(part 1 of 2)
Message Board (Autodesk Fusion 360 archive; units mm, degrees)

design "Message Board" references "MatrixPortal Mount", "Side Panel", "16x32 LED Panel", "Connector Bracket", "5778 Matrix Portal S3", "Top Panel with Cutout", "Top/Bottom Panel"
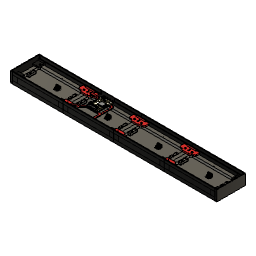
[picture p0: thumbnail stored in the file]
component_insert "Component Insert1"
component_insert "Component Insert2"
component_insert "Component Insert3"
component_insert "Component Insert4"
component_insert "Component Insert5"
component_insert "Component Insert6"
component_insert "Component Insert7"
component_insert "Component Insert8"
component_insert "Component Insert9"
component_insert "Component Insert10"
component_insert "Component Insert12"
component_insert "Component Insert13"
component_insert "Component Insert14"
component_insert "Component Insert16"
component_insert "Component Insert17"
component_insert "Component Insert18"
component_insert "Component Insert19"
component_insert "Component Insert20"
component_insert "Component Insert21"
component_insert "Component Insert22"
component_insert "Component Insert23"
position "Position1"
sketch "Sketch1" plane through (0, 0, 0) normal (0, 0, 1) x axis (1, 0, 0)
  line L1 (-777, 0) -> (0, 0)
  line L2 (-777, -103.75) -> (-777, 0)
  line L3 (0, -103.75) -> (-777, -103.75)
  line L4 (0, 0) -> (0, -103.75)
  point P1 (0, 0)
  point P2 (0, 0)
  point P3 (-777, 0)
  point P5 (0, -103.75)
  horizontal L1
  vertical L2
  horizontal L3
  vertical L4
  coincident P1 P2
  dimension "d1" distance P2 P3 = 777
  dimension "d2" distance P2 P5 = 103.75
extrude "Extrude1" new body sketch "Sketch1" along normal blind 3 bodies "Acrylic Panel"
move "Move1"
position "Position2"
component_insert "Component Insert24"
named bodies: "Acrylic Panel"

design "Side Panel"
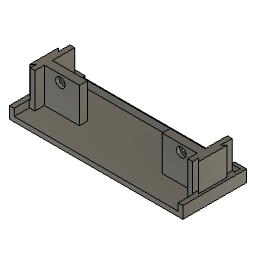
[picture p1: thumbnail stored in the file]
sketch "Sketch1" plane through (0, 0, 0) normal (0, 0, 1) x axis (1, 0, 0)
  line L1 (109, 0) -> (0, 0)
  line L2 (109, 40) -> (109, 0)
  line L3 (0, 40) -> (109, 40)
  line L4 (0, 0) -> (0, 40)
  line L5 (106, 0) -> (3, 0)
  line L6 (106, 34.5) -> (106, 0)
  line L7 (3, 38) -> (105.9999, 38)
  line L8 (3, 0) -> (3, 34.5)
  line L9 (1.5, 11.25) -> (1.5, 29.25)
  line L10 (3.5, 13.25) -> (1.5, 11.25)
  line L11 (3.5, 9.5) -> (3.5, 13.25)
  line L12 (6.5, 9.5) -> (3.5, 9.5)
  line L13 (6.5, 15.5) -> (6.5, 9.5)
  line L14 (28.5, 15.5) -> (6.5, 15.5)
  line L15 (28.5, 20.5) -> (28.5, 15.5)
  line L16 (6.5, 20.5) -> (28.5, 20.5)
  line L17 (6.5, 34.5) -> (6.5, 20.5)
  line L18 (3.5, 34.5) -> (6.5, 34.5)
  line L19 (3.5, 27.25) -> (1.5, 29.25)
  line L20 (3.5, 34.5) -> (3.5, 27.25)
  line L21 (54.5, 40) -> (54.5, 0)
  line L22 (102.5, 9.5) -> (105.5, 9.5)
  line L23 (102.5, 15.5) -> (102.5, 9.5)
  line L24 (80.5, 15.5) -> (102.5, 15.5)
  line L25 (80.5, 20.5) -> (80.5, 15.5)
  line L26 (102.5, 20.5) -> (80.5, 20.5)
  line L27 (102.5, 34.5) -> (102.5, 20.5)
  line L28 (105.5, 34.5) -> (102.5, 34.5)
  line L29 (105.5, 34.5) -> (105.5, 27.25)
  line L30 (105.5, 27.25) -> (107.5, 29.25)
  line L31 (107.5, 11.25) -> (107.5, 29.25)
  line L32 (105.5, 13.25) -> (107.5, 11.25)
  line L33 (105.5, 9.5) -> (105.5, 13.25)
  line L34 (3, 34.5) -> (3.5, 34.5)
  line L35 (3, 9.5) -> (3.5, 9.5)
  line L36 (106, 9.5) -> (105.5, 9.5)
  line L37 (106, 34.5) -> (105.5, 34.5)
  line L38 (2, 38) -> (3, 38)
  line L39 (2, 34.5) -> (2, 38)
  line L40 (3, 34.5) -> (2, 34.5)
  line L41 (107, 38) -> (105.9999, 38)
  line L42 (107, 34.5) -> (106, 34.5)
  line L43 (107, 38) -> (107, 34.5)
  point P1 (0, 0)
  point P2 (0, 0)
  point P6 (3, 0)
  point P22 (54.5, 0)
  point P23 (54.5, 40)
  point P10 (1.5, 29.25)
  point P33 (107.5, 29.25)
  point P11 (1.5, 11.25)
  point P34 (107.5, 11.25)
  point P12 (3.5, 13.25)
  point P35 (105.5, 13.25)
  point P13 (3.5, 9.5)
  point P24 (105.5, 9.5)
  point P14 (6.5, 9.5)
  point P25 (102.5, 9.5)
  point P15 (6.5, 15.5)
  point P26 (102.5, 15.5)
  point P16 (28.5, 15.5)
  point P27 (80.5, 15.5)
  point P17 (28.5, 20.5)
  point P28 (80.5, 20.5)
  point P18 (6.5, 20.5)
  point P29 (102.5, 20.5)
  point P19 (6.5, 34.5)
  point P30 (102.5, 34.5)
  point P20 (3.5, 34.5)
  point P31 (105.5, 34.5)
  point P21 (3.5, 27.25)
  point P32 (105.5, 27.25)
  point P37 (3, 9.5)
  point P38 (105.5, 9.5)
  point P40 (105.5, 34.5)
  point P36 (3, 34.5)
  point P41 (106, 34.5)
  point P39 (106, 9.5)
  point P5 (0, 40)
  point P43 (2, 34.5)
  point P45 (107, 34.5)
  horizontal L1
  vertical L2
  horizontal L3
  vertical L4
  coincident P1 P2
  horizontal L5
  vertical L6
  horizontal L7
  vertical L8
  coincident L1 P6
  parallel L4 L9
  parallel L8 L11
  perpendicular L11 L12
  perpendicular L12 L13
  perpendicular L13 L14
  perpendicular L14 L15
  perpendicular L15 L16
  perpendicular L16 L17
  perpendicular L8 L18
  vertical L20
  midpoint L5 P22
  midpoint L3 P23
  symmetric P10 L21 P33
  symmetric P11 L21 P34
  symmetric P12 L21 P35
  symmetric P13 L21 P24
  symmetric P14 L21 P25
  symmetric P15 L21 P26
  symmetric P16 L21 P27
  symmetric P17 L21 P28
  symmetric P18 L21 P29
  symmetric P19 L21 P30
  symmetric P20 L21 P31
  symmetric P21 L21 P32
  perpendicular L8 L34
  coincident L8 P37
  perpendicular L8 L35
  symmetric P13 L21 P38
  symmetric P20 L21 P40
  symmetric L21 P36 P41
  symmetric L21 P37 P39
  perpendicular L8 L38
  perpendicular L38 L39
  horizontal L40
  perpendicular L6 L41
  perpendicular L6 L42
  vertical L43
  dimension "d2" distance P2 P5 = 40
  dimension "d3" distance L4 L8 = 3
  dimension "d4" distance L2 L6 = 3
  dimension "d5" distance L3 L7 = 2
  dimension "d6" distance P10 P11 = 18
  dimension "d8" distance P13 P14 = 3
  dimension "d9" distance P14 P15 = 6
  dimension "d10" distance P16 P17 = 5
  dimension "d11" distance P17 P18 = 22
  dimension "d12" distance P18 P19 = 14
  dimension "d13" distance P19 P20 = 3
  dimension "d15" distance L9 L11 = 2
  dimension "d16" distance L9 L20 = 2
  dimension "d17" distance P10 L18 = 5.25
  dimension "d18" distance L3 P10 = 10.75
  dimension "d19" distance L4 L9 = 1.5
  dimension "d26" angle L19 L20 = 45
  dimension "d27" angle L10 L11 = 45
  dimension "d54" distance L17 L27 = 96
  dimension "d58" distance P36 P43 = 1
  dimension "d59" distance P41 P45 = 1
extrude "Extrude1" new body sketch "Sketch1" profile of L1 L2 L3 L4 L5 L6 L7 L8 L9 L10 L11 L12 L13 L14 L15 L16 L17 L18 L19 L20 L22 L23 L24 L25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 along normal blind 3
extrude "Extrude2" add sketch "Sketch1" profile of L1 L2 L3 L4 L6 L7 L8 L9 L10 L11 L12 L13 L14 L15 L16 L17 L18 L19 L20 L22 L23 L24 L25 L26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 along normal blind 7.5
extrude "Extrude3" add sketch "Sketch1" profile of L6 L8 L9 L10 L11 L12 L13 L14 L15 L16 L17 L18 L19 L20 L22 L23 L24 L25 L26 L27 L28 L29 L30 L31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 along normal blind 25
sketch "Sketch2" plane through (0, 0, 7.5) normal (0, 0, 1) x axis (-1, 0, 0)
  line L1 (-107.5, -29.25) -> (-105.5, -27.25)
  line L2 (-107.5, -11.25) -> (-107.5, -29.25)
  line L3 (-105.5, -13.25) -> (-107.5, -11.25)
  line L4 (-105.5, -9.5) -> (-105.5, -13.25)
  line L5 (-106, -9.5) -> (-105.5, -9.5)
  line L6 (-109, 0) -> (-106, 0)
  line L7 (-109, -40) -> (-109, 0)
  line L8 (0, -40) -> (-109, -40)
  line L9 (0, 0) -> (0, -40)
  line L10 (-3.5, -9.5) -> (-3, -9.5)
  line L11 (-3.5, -13.25) -> (-3.5, -9.5)
  line L12 (-1.5, -11.25) -> (-3.5, -13.25)
  line L13 (-1.5, -29.25) -> (-1.5, -11.25)
  line L14 (-3.5, -27.25) -> (-1.5, -29.25)
  line L15 (-3.5, -34.5) -> (-3.5, -27.25)
  line L16 (-2, -34.5) -> (-3.5, -34.5)
  line L17 (-105.5, -34.5) -> (-107, -34.5)
  line L18 (-105.5, -27.25) -> (-105.5, -34.5)
  line L19 (-7.5, -38) -> (-7.5, -40)
  line L20 (-101.5, -38) -> (-101.5, -40)
  line L21 (-101.5, -40) -> (-7.5, -40)
  line L22 (-101.5, -38) -> (-7.5, -38)
  line L23 (-106, 0) -> (-106, -9.5)
  line L24 (-3, 0) -> (0, 0)
  line L25 (-3, -9.5) -> (-3, 0)
  line L26 (-2, -38) -> (-2, -34.5)
  line L27 (-107, -38) -> (-2, -38)
  line L28 (-107, -34.5) -> (-107, -38)
  point P23 (-7.5, -40)
  point P25 (-101.5, -40)
  coincident L8 P23
  coincident L8 P25
  dimension "d28" distance L7 L20 = 7.5
  dimension "d29" distance L9 L19 = 7.5
split "Split1" bodies "Side Panel"
chamfer "Chamfer1" distance 1.5
combine "Combine1"
sketch "Sketch3" plane through (0, 20.5, 0) normal (0, 1, 0) x axis (-1, 0, 0)
  line L1 (-6.5, 25) -> (-6.5, 3)
  line L2 (-28.5, 25) -> (-6.5, 25)
  line L3 (-28.5, 3) -> (-28.5, 25)
  line L4 (-6.5, 25) -> (-6.5, 3)
  line L5 (-102.5, 25) -> (-102.5, 3)
  line L6 (-102.5, 3) -> (-80.5, 3)
  line L7 (-101.5, 7.5) -> (-109, 7.5)
  line L8 (-101.5, 7.5) -> (-7.5, 7.5)
  line L9 (-6.5, 3) -> (-28.5, 3)
  circle C1 centre (-16.5, 20.5) radius 1.6
  circle C2 centre (-16.5, 20.5) radius 3
  circle C3 centre (-24.5, 15.5) radius 1.4
  circle C4 centre (-92.5, 20.5) radius 1.6
  circle C5 centre (-92.5, 20.5) radius 3
  point P6 (-16.5, 20.5)
  point P7 (-16.5, 20.5)
  point P10 (-24.5, 15.5)
  point P12 (-92.5, 20.5)
  point P11 (-92.5, 20.5)
  concentric C1 C2
  concentric C4 C5
  dimension "d31" diameter C1 = 3.2
  dimension "d32" diameter C2 = 6
  dimension "d33" distance P6 L4 = 10
  dimension "d35" diameter C3 = 2.8
  dimension "d36" distance P7 P10 = 5
  dimension "d37" distance L4 P10 = 18
  dimension "d38" diameter C4 = 3.2
  dimension "d39" diameter C5 = 6
  dimension "d40" distance P12 L5 = 10
  dimension "d55" distance P11 L7 = 13
  dimension "d56" distance P7 L8 = 13
extrude "Extrude4" cut sketch "Sketch3" profile of C3 against normal blind 3
extrude "Extrude5" cut sketch "Sketch3" profile of C1 C4 against normal blind 5
extrude "Extrude6" cut sketch "Sketch3" profile of C1 C2 C4 C5 blind -2 from offset -3
named bodies: "Side Panel"

design "Top Panel with Cutout"
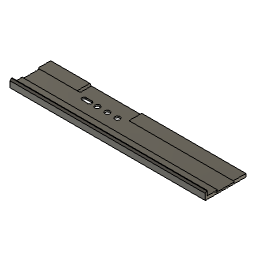
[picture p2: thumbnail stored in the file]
sketch "Sketch1" plane through (0, 0, 0) normal (1, 0, 0) x axis (0, 1, 0)
  line L1 (-38, 3) -> (-38, 7.5)
  line L2 (-34.75, 3) -> (-38, 3)
  line L3 (-38, 7.5) -> (-40, 7.5)
  line L4 (-40, 7.5) -> (-40, 0)
  line L5 (0, 0) -> (-40, 0)
  line L6 (-28, 3) -> (-34.75, 3)
  line L7 (-29.5, 1.5) -> (-28, 3)
  line L8 (-11, 1.5) -> (-29.5, 1.5)
  line L9 (-12.5, 3) -> (-11, 1.5)
  line L10 (-11, 2.1821) -> (-11, 1.5)
  line L11 (-12.5, 3) -> (0, 3)
  line L12 (0, 3) -> (0, 0)
  point P5 (0, 0)
  point P8 (0, 0)
  point P15 (0, 0)
  point P1 (0, 0)
  point P2 (-40, 7.5)
  point P4 (-38, 7.5)
  point P11 (-29.5, 1.5)
  point P12 (-11, 1.5)
  point P6 (-34.75, 3)
  point P10 (-28, 3)
  coincident P5 P8
  perpendicular L3 L4
  perpendicular L1 L3
  perpendicular L4 L5
  perpendicular L1 L2
  parallel L5 L8
  coincident P5 P15
  perpendicular L5 L12
  perpendicular L11 L12
  coincident P1 P5
  dimension "d9" distance P2 P4 = 2
  dimension "d15" distance L3 L5 = 7.5
  dimension "d25" angle L6 L7 = 45
  dimension "d26" distance P11 P12 = 18.5
  dimension "d27" angle L9 L10 = 45
  dimension "d32" angle L9 L11 = 45
  dimension "d34" distance L5 L11 = 3
  dimension "d35" distance L5 L8 = 1.5
  dimension "d36" distance L5 L6 = 3
  dimension "d37" distance L4 L12 = 40
  dimension "d39" distance P6 P10 = 6.75
  dimension "d40" distance P6 L1 = 3.25
  dimension "d42" distance P12 L12 = 11
extrude "Extrude1" new body sketch "Sketch1" profile of L1 L2 L3 L4 L5 L6 L7 L8 L9 L11 L12 along normal blind 192 bodies "Top Panel with Cutout"
chamfer "Chamfer1" distance 1.5
sketch "Sketch2" plane through (0, -40, 0) normal (0, -1, 0) x axis (1, 0, 0)
  line L1 (0, 6) -> (192, 6)
  line L2 (0, 0) -> (0, 6)
  line L3 (192, 0) -> (0, 0)
  line L4 (192, 6) -> (192, 0)
sketch "Sketch3" plane through (0, 0, 3) normal (0, 0, 1) x axis (-1, 0, 0)
  line L1 (0, 12.5) -> (0, 0)
  line L2 (-192, 12.5) -> (0, 12.5)
  line L3 (-192, 0) -> (-192, 12.5)
  line L4 (0, 0) -> (-192, 0)
  line L5 (-40, 0) -> (-40, 12.5)
  line L6 (-88, 12.5) -> (-88, 0)
  line L7 (-88, 0) -> (-40, 0)
  line L8 (-88, 12.5) -> (-40, 12.5)
  point P6 (-40, 12.5)
  point P7 (-40, 0)
  point P8 (-88, 0)
  point P9 (-88, 12.5)
  coincident L2 P6
  coincident L4 P7
  perpendicular L4 L5
  coincident L4 P8
  coincident L2 P9
  perpendicular L2 L6
  perpendicular L6 L7
  dimension "d43" distance L5 L6 = 48
  dimension "d63" distance L1 L5 = 40
extrude "Extrude2" cut sketch "Sketch3" profile of L2 L4 L5 L6 L7 L8 along a picked direction blind -1.5
sketch "Sketch4" plane through (0, 0, 1.5) normal (0, 0, 1) x axis (-1, 0, 0)
  line L1 (0, 11) -> (-40, 11)
  line L2 (0, 29.5) -> (0, 11)
  line L3 (-192, 29.5) -> (0, 29.5)
  line L4 (-192, 11) -> (-192, 29.5)
  line L5 (-88, 11) -> (-192, 11)
  line L6 (-88, 0) -> (-88, 11)
  line L7 (-40, 0) -> (-88, 0)
  line L8 (-40, 11) -> (-40, 0)
  line L9 (-55.25, 12.5) -> (-45.25, 12.5)
  line L10 (-55.25, 16.5) -> (-55.25, 12.5)
  line L11 (-45.25, 16.5) -> (-55.25, 16.5)
  line L12 (-45.25, 12.5) -> (-45.25, 16.5)
  line L13 (-86.3147, 14.5) -> (-42.264, 14.5)
  line L14 (-40, 0) -> (-40, 12.5)
  circle C1 centre (-60.45, 14.5) radius 2.5
  circle C2 centre (-70.3, 14.5) radius 2.5
  circle C3 centre (-80.15, 14.5) radius 2.5
  point P14 (-60.45, 14.5)
  point P15 (-70.3, 14.5)
  point P16 (-80.15, 14.5)
  point P10 (-45.25, 12.5)
  point P11 (-55.25, 12.5)
  point P13 (-45.25, 16.5)
  horizontal L9
  vertical L10
  horizontal L11
  vertical L12
  coincident P14 L13
  coincident P15 L13
  coincident P16 L13
  horizontal L13
  dimension "d47" distance P10 P11 = 10
  dimension "d48" diameter C1 = 5
  dimension "d49" diameter C2 = 5
  dimension "d50" diameter C3 = 5
  dimension "d51" distance P14 P15 = 9.85
  dimension "d52" distance P15 P16 = 9.85
  dimension "d53" distance L10 P14 = 5.2
  dimension "d54" distance L7 L13 = 14.5
  dimension "d55" distance L12 L14 = 5.25
  dimension "d56" distance P10 P13 = 4
  dimension "d57" distance L9 L13 = 2 (= "d56 / 2")
extrude "Extrude3" cut sketch "Sketch4" profile of L9 L10 L11 L12 C1 C2 C3 along a picked direction blind -3
fillet "Fillet1" radius 2
chamfer "Chamfer2" distance 1.5
named bodies: "Top Panel with Cutout"

design "Power Plug" references "Matrix Power Pin"
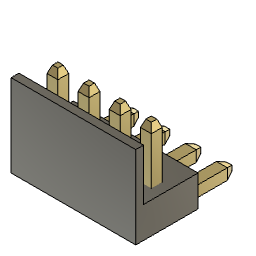
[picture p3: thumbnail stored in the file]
component_insert "Component Insert1"
sketch "Sketch1" plane through (0, 0, 0) normal (0, 0, 1) x axis (1, 0, 0)
  line L1 (-16, 0) -> (0, 0)
  line L2 (-16, -8) -> (-16, 0)
  line L3 (0, -8) -> (-16, -8)
  line L4 (0, 0) -> (0, -8)
  line L5 (-16, -7) -> (0, -7)
  point P1 (0, 0)
  point P2 (0, 0)
  point P6 (0, -7)
  point P7 (-16, -7)
  point P3 (-16, 0)
  point P5 (0, -8)
  horizontal L1
  vertical L2
  horizontal L3
  vertical L4
  coincident P1 P2
  coincident L4 P6
  coincident L2 P7
  perpendicular L2 L5
  dimension "d1" distance P2 P3 = 16
  dimension "d2" distance P2 P5 = 8
  dimension "d3" distance L3 L5 = 1
extrude "Extrude1" new body sketch "Sketch1" profile of L1 L2 L4 L5 along normal blind 4
extrude "Extrude2" add sketch "Sketch1" profile of L2 L3 L4 L5 along normal blind 10.6
component_insert "Component Insert2"
component_insert "Component Insert3"
component_insert "Component Insert4"

design "Matrix Power Pin"
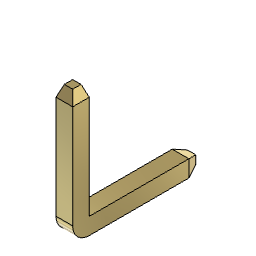
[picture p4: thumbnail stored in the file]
parameter "param_e" = 4 comment "Row Pitch"
parameter "param_d" = 4 comment "Col Pitch"
parameter "param_L" = 4 comment "Body Height"
parameter "param_b" = 1.4 comment "Terminal Width"
parameter "param_D" = 6 comment "Body Length"
parameter "param_E" = 20 comment "Lead Span 1"
parameter "param_E1" = 8 comment "Body Width"
parameter "param_L1" = 1.5 comment "Terminal Tail Length"
parameter "param_L2" = 6.3 comment "Post Length"
step "surface_mount_pin_header_straight"
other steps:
extrude "Extrude1" new body sketch "SketchBody" profile of L1 L2 L3 L4 along normal blind 6 (= "param_D")
chamfer "Chamfer1" distance 0.5 distance 0.5
chamfer "Chamfer2" distance 0.5 distance 0.5
sweep "Sweep2" sketch "SketchPin" TwistAngle 0 TaperAngle 0
chamfer "Chamfer3" distance 0.35 (= "param_b / 4") distance 0.9333 (= "param_b / 1.5")
chamfer "Chamfer4" distance 0.35 (= "param_b / 4") distance 0.9333 (= "param_b / 1.5")
create_component "CreateComponent5"
work_plane "WorkPlane1" AlongDistance -3 (= "( -param_D + param_d * ( cols - 1 ) ) / 2")
sketch "SketchBody" plane through (-3, 0, 0) normal (1, 0, 0) x axis (0, 0, -1)
  line L1 (-1.5, 4) -> (-4, 4)
  line L2 (-1.5, -4) -> (-1.5, 4)
  line L3 (-4, -4) -> (-1.5, -4)
  line L4 (-4, 4) -> (-4, -4)
  line L5 (-1.5, -4) -> (-4, 4)
  line L6 (-4, -4) -> (-1.5, 4)
  line L7 (-11, 0) -> (-1.4, 0)
  line L8 (-0.7, 10) -> (-0.7, 0.7)
  line L9 (0, 0) -> (-0.7, 0)
  arc A1 centre (-1.4, 0.7) radius 0.7 clockwise from (-0.7, 0.7) to (-1.4, 0)
  point P6 (-2.75, 0)
  point P7 (-0.7, 0)
  point P1 (0, 0)
  point P2 (-4, 4)
  point P3 (-1.5, 4)
  point P4 (-1.5, -4)
  point P9 (-0.7, 10)
  point P11 (-0.7, 0.7)
  point P8 (-11, 0)
  point P10 (-1.4, 0)
  horizontal L1
  horizontal L3
  vertical L2
  vertical L4
  midpoint L5 P6
  horizontal L7
  vertical L8
  horizontal L9
  coincident P7 L7
  coincident P7 L8
  tangent L7 A1
  tangent L8 A1
  dimension "d210" distance P1 P6 = 2.75 (= "( param_L - param_L1 ) / 2 + param_L1")
  dimension "d211" distance P1 P6 = 0 (= "param_E / 2 - ( param_E - param_e * ( rows - 1 ) ) / 2")
  dimension "d212" distance P2 P3 = 2.5 (= "param_L - param_L1")
  dimension "d213" distance P3 P4 = 8 (= "param_E1")
  dimension "d233" distance P9 P11 = 9.3 (= "param_E / 2 - param_b / 2")
  dimension "d234" distance P8 P10 = 9.6 (= "param_L + param_L2 - param_b / 2")
  dimension "d235" distance P1 P7 = 0.7 (= "param_b / 2")
  dimension "d236" radius A1 = 0.7 (= "param_b / 2")
work_plane "WorkPlane2" AlongDistance 4 (= "param_L")
sketch "SketchBodySlot" plane through (0, 0, 4) normal (0, 0, 1) x axis (1, 0, 0)
  line L1 (2.5, -4) -> (1.5, -4)
  line L2 (2, -3.5) -> (2.5, -4)
  line L3 (1.5, -4) -> (2, -3.5)
  point P1 (0, 0)
  point P4 (2, -3.5)
  point P2 (1.5, -4)
  equal L2 L3
  horizontal L1
  dimension "d221" distance P1 P4 = 2 (= "param_d / 2")
  dimension "d222" distance P1 P2 = 4 (= "param_E1 - ( param_E1 - param_e * ( rows - 1 ) ) / 2")
sweep "Sweep1" sketch "SketchBodySlot" TwistAngle 0 TaperAngle 0
rectangular_pattern "R-Pattern1" uSpaceDistance 4 (= "param_d") vSpaceDistance 0
work_plane "WorkPlane3" AlongDistance 10.3 (= "param_L + param_L2")
sketch "SketchPin" plane through (0, 0, 10.3) normal (0, 0, 1) x axis (1, 0, 0)
  line L1 (-0.7, -0.7) -> (0.7, -0.7)
  line L2 (-0.7, 0.7) -> (-0.7, -0.7)
  line L3 (0.7, 0.7) -> (-0.7, 0.7)
  line L4 (0.7, -0.7) -> (0.7, 0.7)
  line L5 (-0.7, 0.7) -> (0.7, -0.7)
  line L6 (0.7, 0.7) -> (-0.7, -0.7)
  point P6 (0, 0)
  point P1 (0, 0)
  point P2 (0.7, -0.7)
  point P3 (-0.7, -0.7)
  point P4 (-0.7, 0.7)
  horizontal L1
  horizontal L3
  vertical L2
  vertical L4
  midpoint L5 P6
  dimension "d238" distance P1 P6 = 0
  dimension "d239" distance P1 P6 = 0
  dimension "d240" distance P2 P3 = 1.4 (= "param_b")
  dimension "d241" distance P3 P4 = 1.4 (= "param_b")

design "MatrixPortal Mount" references "5778 Matrix Portal S3", "Top Panel with Cutout", "16x32 LED Panel", "Connector Bracket"
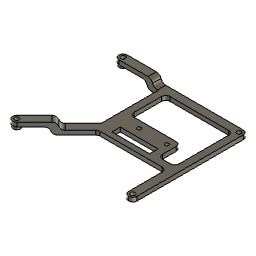
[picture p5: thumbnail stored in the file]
component_insert "Component Insert2"
component_insert "Component Insert3"
component_insert "Component Insert6"
component_insert "Component Insert7"
component_insert "Component Insert8"
component_insert "Component Insert9"
position "Position4"
component_insert "Component Insert11"
position "Position5"
position "Position6"
position "Position7"
position "Position8"
sketch "Sketch1" plane through (0, 0, 12.75) normal (0, 0, 1) x axis (-1, 0, 0)
  line L1 (-12, -78.5) -> (-12, -17.5)
  line L2 (-175, -83.5) -> (-17, -83.5)
  line L3 (-180, -17.5) -> (-180, -78.5)
  line L4 (-17, -12.5) -> (-175, -12.5)
  line L5 (0, 0) -> (0, -96)
  line L6 (-192, 0) -> (0, 0)
  line L7 (-192, -96) -> (-192, 0)
  line L8 (0, -96) -> (-192, -96)
  line L9 (-44.2426, -37) -> (-13, -5.7574)
  line L10 (-8.7574, -10) -> (-13, -5.7574)
  line L11 (-99, -7) -> (-99, -89)
  line L12 (-10, -83) -> (-10, -89)
  line L13 (-50.2, -40.8) -> (-77.2, -40.8)
  line L14 (-50.2, -46.8) -> (-50.2, -40.8)
  line L15 (-77.2, -46.8) -> (-50.2, -46.8)
  line L16 (-77.2, -40.8) -> (-77.2, -46.8)
  line L17 (-10, -89) -> (-99, -89)
  line L18 (-41, -83) -> (-10, -83)
  line L19 (-41, -42.2426) -> (-41, -83)
  line L20 (-33, -83) -> (-33, -89)
  line L21 (-37, -83) -> (-37, -89)
  line L22 (-93, -7) -> (-99, -7)
  line L23 (-93, -37) -> (-93, -7)
  line L24 (-44.2426, -37) -> (-93, -37)
  line L25 (-27.1421, -19.8995) -> (-22.8995, -24.1421)
  line L26 (-25.7279, -26.9706) -> (-29.9706, -22.7279)
  line L27 (-41, -42.2426) -> (-8.7574, -10)
  line L28 (-94, -84) -> (-46, -84)
  line L29 (-94, -57.8096) -> (-94, -84)
  line L30 (-46, -57.8096) -> (-94, -57.8096)
  line L31 (-46, -84) -> (-46, -57.8096)
  line L32 (-82.2, -57.8096) -> (-94, -57.8096)
  line L33 (-82.2, -42) -> (-82.2, -57.8096)
  line L34 (-94, -42) -> (-82.2, -42)
  line L35 (-94, -57.8096) -> (-94, -42)
  circle C1 centre (-179, -86) radius 1.25
  circle C2 centre (-13, -10) radius 1.25
  circle C3 centre (-96, -86) radius 1.25
  circle C4 centre (-179, -10) radius 1.25
  circle C5 centre (-96, -10) radius 1.25
  circle C6 centre (-13, -86) radius 1.25
  circle C7 centre (-7.5, -78) radius 1.25
  circle C8 centre (-184.5, -18) radius 1.25
  arc A1 centre (-17, -17.5) radius 5 clockwise from (-17, -12.5) to (-12, -17.5)
  arc A2 centre (-17, -78.5) radius 5 clockwise from (-12, -78.5) to (-17, -83.5)
  arc A3 centre (-175, -78.5) radius 5 clockwise from (-175, -83.5) to (-180, -78.5)
  arc A4 centre (-175, -17.5) radius 5 clockwise from (-180, -17.5) to (-175, -12.5)
  circle C9 centre (-57.7745, -52.8096) radius 1.35
  circle C10 centre (-77.5865, -52.8096) radius 1.35
  circle C11 centre (-96, -10) radius 1.6
  circle C12 centre (-96, -86) radius 1.6
  circle C13 centre (-13, -86) radius 1.6
  circle C14 centre (-13, -10) radius 1.6
  circle C15 centre (-13, -10) radius 2.65
  circle C16 centre (-13, -86) radius 2.65
  circle C17 centre (-77.5865, -52.8096) radius 1.25
  point P6 (-96, -10)
  point P33 (-96, -10)
  point P4 (-96, -86)
  point P34 (-96, -86)
  point P3 (-13, -10)
  point P36 (-13, -10)
  point P7 (-13, -86)
  point P35 (-13, -86)
  point P39 (-99, -7)
  point P41 (-99, -7)
  point P49 (-33, -89)
  point P50 (-33, -83)
  point P51 (-37, -89)
  point P52 (-37, -83)
  point P56 (-27.1421, -19.8995)
  point P57 (-29.9706, -22.7279)
  point P58 (-25.7279, -26.9706)
  point P55 (-22.8995, -24.1421)
  point P44 (-77.2, -40.8)
  point P45 (-50.2, -40.8)
  point P47 (-77.2, -46.8)
  point P30 (-10, -89)
  point P42 (-10, -83)
  point P38 (-13, -86)
  point P53 (-93, -7)
  point P31 (-57.7745, -52.8096)
  perpendicular L9 L10
  vertical L11
  coincident P6 P33
  coincident P4 P34
  coincident P3 P36
  coincident P7 P35
  concentric C14 C15
  concentric C13 C16
  coincident P39 P41
  horizontal L13
  vertical L14
  horizontal L15
  vertical L16
  horizontal L17
  vertical L12
  perpendicular L12 L18
  vertical L19
  coincident L17 P49
  coincident L18 P50
  perpendicular L18 L20
  coincident L17 P51
  coincident L18 P52
  perpendicular L18 L21
  perpendicular L11 L22
  perpendicular L6 L23
  coincident L9 P56
  perpendicular L9 L25
  coincident L9 P57
  horizontal L24
  perpendicular L10 L27
  coincident P58 L27
  coincident P55 L27
  concentric C10 C17
  horizontal L28
  vertical L29
  horizontal L30
  vertical L31
  horizontal L32
  vertical L33
  horizontal L34
  vertical L35
  dimension "d1" diameter C9 = 2.7
  dimension "d13" distance P4 L11 = 3
  dimension "d28" diameter C11 = 3.2
  dimension "d29" diameter C12 = 3.2
  dimension "d30" diameter C13 = 3.2
  dimension "d31" diameter C14 = 3.2
  dimension "d47" diameter C15 = 5.3
  dimension "d48" diameter C16 = 5.3
  dimension "d71" distance P44 P45 = 27
  dimension "d72" distance P44 P47 = 6
  dimension "d81" distance P30 P42 = 6
  dimension "d82" distance P3 L10 = 3
  dimension "d84" distance P38 L12 = 3
  dimension "d85" distance P38 L17 = 3
  dimension "d86" distance L20 L21 = 4
  dimension "d87" distance L12 L20 = 23
  dimension "d88" distance L12 L19 = 31
  dimension "d90" distance L25 L26 = 4
  dimension "d91" distance L10 L25 = 20
  dimension "d92" distance L17 L24 = 52
  dimension "d93" distance P39 P53 = 6
  dimension "d94" distance P33 L22 = 3
  dimension "d95" distance L13 L24 = 3.8
  dimension "d96" distance L14 L19 = 9.2
  dimension "d97" angle L19 L27 = 135
  dimension "d98" distance L9 L27 = 6
  dimension "d99" distance L9 P36 = 3
  dimension "d100" distance L19 L31 = 5
  dimension "d101" distance L17 L28 = 5
  dimension "d102" distance L11 L29 = 5
  dimension "d103" distance P31 L30 = 5
  dimension "d104" distance L24 L34 = 5
  dimension "d105" distance L16 L33 = 5
  dimension "d10" R-Pattern1-uDistance = -19.812
  dimension "d11" R-Pattern1-vDistance = -40.64
extrude "Extrude1" new body sketch "Sketch1" profile of L2 L4 L9 C9 C10 C11 C12 L11 L13 L14 L15 L16 L17 L18 L19 L20 L21 L22 L23 L24 L25 L26 L27 L28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 along normal blind 3 bodies "MatrixPortal Mount"
extrude "Extrude2" add sketch "Sketch1" profile of L2 L9 L17 L18 L20 L21 L25 L26 L27 along normal blind 8
extrude "Extrude3" add sketch "Sketch1" profile of A1 A2 L2 L4 L9 L10 C13 C14 C15 C16 L12 L17 L18 L20 L21 L25 L26 L27 blind 3 from offset 5
fillet "Fillet1" radius 3.5
fillet "Fillet2" radius 3
extrude "Extrude4" add sketch "Sketch1" profile of C13 C14 C15 C16 blind 2 from offset 3
named bodies: "MatrixPortal Mount"

design "5778 Matrix Portal S3"
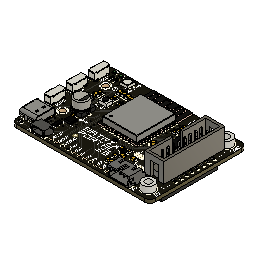
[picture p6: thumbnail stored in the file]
part number: RED
part number: 10uF
part number: AP2112K-3.3
part number: WS2812B_3535FULL
part number: 10K
part number: 5.1K Pack
part number: USB TYPE C
part number: TL3330AF260QG
part number: 100uF/6.3V
part number: 74AHCT245
part number: SEWTAP_SMTNUTM3
part number: STEMMA_I2C_QT
part number: JST PH 3
part number: 3.6V
part number: LIS3DHTR
part number: FIDUCIAL_1MM
part number: KMR2
part number: ESP32-S3-WROOM
part number: ALS-PT19
part number: MOUNTINGHOLE2.5
pcb "PCB1" BoardHeight 1.57
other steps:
extrude "Extrude1" new body sketch "Sketch1" along normal blind 0.1 bodies "SOLDERJUMPER_2WAY_OPEN_NOPASTE"
extrude "Extrude1" new body sketch "Sketch1" along normal blind 0.1 bodies "1X11_ROUND"
extrude "Extrude1" new body sketch "Sketch1" along normal blind 0.1 bodies "FIDUCIAL_1MM"
extrude "Extrude1" new body sketch "Sketch1" along normal blind 0.1 bodies "PCBFEAT-REV-040"
extrude "Extrude1" new body sketch "Sketch1" along normal blind 0.1 bodies "MOUNTINGHOLE_2.5_PLATED"
extrude "Extrude1" new body sketch "Sketch1" along normal blind 0.1 bodies "S3_MATRIXPORTAL_BOT"
extrude "Extrude1" new body sketch "Sketch1" along normal blind 0.1 bodies "S3_MATRIXPORTAL_TOP"
extrude "Extrude1" new body sketch "Sketch1" along normal blind 0.1 bodies "CHIPLED_0603_NOOUTLINE"
extrude "Extrude1" new body sketch "Sketch1" along normal blind 0.1 bodies "TSSOP20"
extrude "Extrude1" new body sketch "Sketch1" along normal blind 0.1 bodies "JSTPH3"
extrude "Extrude1" new body sketch "Sketch1" along normal blind 0.1 bodies "ALS-PT19-315C"
extrude "Extrude1" new body sketch "Sketch1" along normal blind 0.1 bodies "0805-NO"
extrude "Extrude1" new body sketch "Sketch1" along normal blind 0.1 bodies "SOT23-DBV"
extrude "Extrude1" new body sketch "Sketch1" along normal blind 0.1 bodies "LED3535_FULLPADS"
extrude "Extrude1" new body sketch "Sketch1" along normal blind 0.1 bodies "0603-NO"
extrude "Extrude1" new body sketch "Sketch1" along normal blind 0.1 bodies "RESPACK_4X0603"
extrude "Extrude1" new body sketch "Sketch1" along normal blind 0.1 bodies "USB_C_CUSB31-CFM2AX-01-X"
extrude "Extrude1" new body sketch "Sketch1" along normal blind 0.1 bodies "SMT_NUT_3MM"
extrude "Extrude1" new body sketch "Sketch1" along normal blind 0.1 bodies "JST_SH4"
extrude "Extrude1" new body sketch "Sketch1" along normal blind 0.1 bodies "SOD-323"
extrude "Extrude1" new body sketch "Sketch1" along normal blind 0.1 bodies "LGA16_3X3MM"
extrude "Extrude1" new body sketch "Sketch1" along normal blind 0.1 bodies "S3-WROOM32"
base_feature "Base Feature1" sketch "Sketch1"
base_feature "Base Feature1" sketch "Sketch1"
base_feature "Base Feature1" sketch "Sketch1"
base_feature "Base Feature1" sketch "Sketch1"
extrude "Extrude1" new body sketch "Sketch1" along normal blind 1.57 bodies "Board"
extrude "Extrude1" new body sketch "Sketch1" along normal blind 0.1 bodies "PANASONIC_D"
base_feature "Base Feature1" sketch "Sketch1"
base_feature "Base Feature1" sketch "Sketch1"
base_feature "Base Feature1" sketch "Sketch1"
base_feature "Base Feature1" sketch "Sketch1"
base_feature "Base Feature1" sketch "Sketch1"
base_feature "Base Feature1" sketch "Sketch1"
base_feature "Base Feature1" sketch "Sketch1"
base_feature "Base Feature1" sketch "Sketch1"
base_feature "Base Feature1" sketch "Sketch1"
base_feature "Base Feature1" sketch "Sketch1"
base_feature "Base Feature1" sketch "Sketch1"
extrude "Extrude2" sketch "Sketch2" blind 1.57
extrude "Extrude1" new body sketch "Sketch1" along normal blind 0.1 bodies "SPST_TACTILE_RA"
extrude "Extrude1" new body sketch "Sketch1" along normal blind 0.1 bodies "BTN_RKB2_4.6X2.8"
extrude "Extrude1" new body sketch "Sketch1" along normal blind 0.1 bodies "2X08_SHROUDEDSMT"
base_feature "Base Feature1" sketch "Sketch1"
base_feature "Base Feature1" sketch "Sketch1"
base_feature "Base Feature1" sketch "Sketch1"
base_feature "Base Feature1" sketch "Sketch1"
extrude "Extrude1" new body sketch "Sketch1" along normal blind 0.1 bodies "2X10_SMT_FEMALE"
base_feature "Base Feature1" sketch "Sketch1"
create_component "CreateComponent1"
sketch "Sketch1" plane through (0, 0, 0) normal (0, 0, 1) x axis (1, 0, 0)
  line L1 (63.5, 2.54) -> (63.5, 41.91)
  line L2 (2.54, 0) -> (60.96, 0)
  line L3 (0, 35.56) -> (0, 2.54)
  line L4 (0.889, 36.449) -> (0, 35.56)
  line L5 (0.889, 39.624) -> (0.889, 36.449)
  line L6 (0, 40.513) -> (0.889, 39.624)
  line L7 (0, 41.91) -> (0, 40.513)
  line L8 (60.96, 44.45) -> (2.54, 44.45)
  arc A1 centre (60.96, 2.54) radius 2.54 clockwise from (63.5, 2.54) to (60.96, 0)
  arc A2 centre (2.54, 2.54) radius 2.54 clockwise from (2.54, 0) to (0, 2.54)
  arc A3 centre (2.54, 41.91) radius 2.54 clockwise from (0, 41.91) to (2.54, 44.45)
  arc A4 centre (60.96, 41.91) radius 2.54 clockwise from (60.96, 44.45) to (63.5, 41.91)
canvas "Canvas1"
canvas "Canvas2"
sketch "Sketch2" plane through (0, 0, 0) normal (0, 0, 1) x axis (1, 0, 0)
  line L1 (2.3, 12.275) -> (2.9, 12.275)
  line L2 (2.9, 12.875) -> (2.3, 12.875)
  line L3 (7.33, 12.875) -> (6.23, 12.875)
  line L4 (6.23, 12.275) -> (7.33, 12.275)
  line L5 (7.33, 4.235) -> (6.23, 4.235)
  line L6 (6.23, 3.635) -> (7.33, 3.635)
  line L7 (2.9, 4.235) -> (2.3, 4.235)
  line L8 (2.3, 3.635) -> (2.9, 3.635)
  circle C1 centre (48.768, 25.21) radius 0.25
  circle C2 centre (52.229, 9.176) radius 0.25
  circle C3 centre (8.89, 5.334) radius 0.25
  circle C4 centre (8.89, 11.176) radius 0.25
  circle C5 centre (45.53, 22.034) radius 0.25
  circle C6 centre (46.292, 29.654) radius 0.25
  circle C7 centre (48.895, 30.036) radius 0.25
  circle C8 centre (9.97, 18.606) radius 0.25
  circle C9 centre (10.478, 32.575) radius 0.25
  circle C10 centre (12.636, 31.814) radius 0.25
  circle C11 centre (17.844, 30.29) radius 0.25
  circle C12 centre (14.922, 38.036) radius 0.25
  circle C13 centre (10.224, 38.418) radius 0.25
  circle C14 centre (11.748, 38.418) radius 0.25
  circle C15 centre (14.288, 43.37) radius 0.25
  circle C16 centre (6.54, 28.892) radius 0.25
  circle C17 centre (2.476, 32.322) radius 0.25
  circle C18 centre (2.604, 24.066) radius 0.25
  circle C19 centre (2.604, 14.668) radius 0.25
  circle C20 centre (23.558, 36.766) radius 0.25
  circle C21 centre (25.336, 36.766) radius 0.25
  circle C22 centre (27.368, 36.766) radius 0.25
  circle C23 centre (29.274, 36.766) radius 0.25
  circle C24 centre (31.052, 36.766) radius 0.25
  circle C25 centre (33.084, 36.766) radius 0.25
  circle C26 centre (34.862, 36.766) radius 0.25
  circle C27 centre (36.64, 36.766) radius 0.25
  circle C28 centre (37.148, 33.972) radius 0.25
  circle C29 centre (34.354, 34.48) radius 0.25
  circle C30 centre (32.449, 33.084) radius 0.25
  circle C31 centre (30.036, 34.734) radius 0.25
  circle C32 centre (29.654, 32.449) radius 0.25
  circle C33 centre (26.226, 34.862) radius 0.25
  circle C34 centre (26.352, 32.702) radius 0.25
  circle C35 centre (23.432, 34.608) radius 0.25
  circle C36 centre (23.432, 32.068) radius 0.25
  circle C37 centre (25.336, 30.29) radius 0.25
  circle C38 centre (23.558, 28.512) radius 0.25
  circle C39 centre (25.336, 25.844) radius 0.25
  circle C40 centre (23.558, 23.94) radius 0.25
  circle C41 centre (26.352, 22.416) radius 0.25
  circle C42 centre (24.574, 21.526) radius 0.25
  circle C43 centre (29.274, 21.4) radius 0.25
  circle C44 centre (28.892, 23.558) radius 0.25
  circle C45 centre (26.606, 24.702) radius 0.25
  circle C46 centre (31.432, 24.956) radius 0.25
  circle C47 centre (32.322, 22.796) radius 0.25
  circle C48 centre (32.068, 20.51) radius 0.25
  circle C49 centre (34.354, 20.384) radius 0.25
  circle C50 centre (36.894, 20.256) radius 0.25
  circle C51 centre (36.386, 22.288) radius 0.25
  circle C52 centre (34.862, 21.78) radius 0.25
  circle C53 centre (34.608, 24.32) radius 0.25
  circle C54 centre (36.386, 26.226) radius 0.25
  circle C55 centre (33.21, 26.86) radius 0.25
  circle C56 centre (33.338, 29.528) radius 0.25
  circle C57 centre (35.75, 28.004) radius 0.25
  circle C58 centre (36.386, 30.162) radius 0.25
  circle C59 centre (34.608, 32.194) radius 0.25
  circle C60 centre (40.322, 36.64) radius 0.25
  circle C61 centre (45.022, 36.512) radius 0.25
  circle C62 centre (50.102, 33.464) radius 0.25
  circle C63 centre (52.26, 5.524) radius 0.25
  circle C64 centre (53.658, 8.192) radius 0.25
  circle C65 centre (49.848, 1.968) radius 0.25
  circle C66 centre (46.926, 2.096) radius 0.25
  circle C67 centre (44.514, 6.16) radius 0.25
  circle C68 centre (45.656, 8.065) radius 0.25
  circle C69 centre (48.578, 22.288) radius 0.25
  circle C70 centre (17.082, 12.636) radius 0.25
  circle C71 centre (13.78, 9.97) radius 0.25
  circle C72 centre (11.62, 2.858) radius 0.25
  circle C73 centre (11.24, 0.952) radius 0.25
  circle C74 centre (2.604, 6.922) radius 0.25
  circle C75 centre (8.7, 3.746) radius 0.25
  circle C76 centre (10.732, 12.51) radius 0.25
  circle C77 centre (40.322, 30.67) radius 0.25
  circle C78 centre (46.038, 24.574) radius 0.25
  circle C79 centre (43.37, 26.226) radius 0.25
  circle C80 centre (46.418, 26.606) radius 0.25
  circle C81 centre (34.862, 11.874) radius 0.25
  circle C82 centre (44.514, 14.034) radius 0.25
  circle C83 centre (41.212, 8.065) radius 0.25
  circle C84 centre (20.574, 17.399) radius 0.25
  circle C85 centre (8.742, 8.001) radius 0.25
  circle C86 centre (9.123, 9.144) radius 0.25
  circle C87 centre (20.574, 16.002) radius 0.25
  circle C88 centre (41.91, 10.35) radius 0.25
  circle C89 centre (44.831, 33.401) radius 0.25
  circle C90 centre (42.037, 6.35) radius 0.25
  circle C91 centre (10.93, 6.858) radius 0.25
  circle C92 centre (17.653, 15.748) radius 0.25
  circle C93 centre (16.256, 13.589) radius 0.25
  circle C94 centre (3.302, 34.671) radius 0.25
  circle C95 centre (17.907, 33.147) radius 0.25
  circle C96 centre (13.843, 38.989) radius 0.25
  circle C97 centre (19.685, 32.766) radius 0.25
  circle C98 centre (46.355, 27.94) radius 0.25
  circle C99 centre (40.259, 34.163) radius 0.25
  circle C100 centre (54.991, 31.115) radius 0.2415
  circle C101 centre (55.499, 28.575) radius 0.2415
  circle C102 centre (48.76, 28.181) radius 0.2415
  circle C103 centre (53.34, 26.035) radius 0.2415
  circle C104 centre (55.372, 23.495) radius 0.2415
  circle C105 centre (55.372, 20.955) radius 0.2415
  circle C106 centre (55.499, 18.415) radius 0.2415
  circle C107 centre (49.403, 26.48) radius 0.25
  circle C108 centre (53.213, 15.875) radius 0.2415
  circle C109 centre (53.213, 13.335) radius 0.2415
  circle C110 centre (59.182, 15.875) radius 0.2415
  circle C111 centre (59.055, 18.415) radius 0.2415
  circle C112 centre (59.055, 20.955) radius 0.2415
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create_component "CreateComponent2" sketch "Sketch1"
sketch "Sketch1" plane through (0, 0, 0) normal (0, 0, 1) x axis (1, 0, 0)
  line L1 (0.45, -1.1) -> (-0.45, -1.1)
  line L2 (0.45, 1.1272) -> (0.45, -1.1)
  line L3 (-0.45, 1.1272) -> (0.45, 1.1272)
  line L4 (-0.45, -1.1) -> (-0.45, 1.1272)
create_component "CreateComponent3" sketch "Sketch1"
sketch "Sketch1" plane through (0, 0, 0) normal (0, 0, 1) x axis (1, 0, 0)
  line L1 (1.106, -0.724) -> (-1.092, -0.724)
  line L2 (1.106, 0.726) -> (1.106, -0.724)
  line L3 (-1.092, 0.726) -> (1.106, 0.726)
  line L4 (-1.092, -0.724) -> (-1.092, 0.726)
create_component "CreateComponent4" sketch "Sketch1"
sketch "Sketch1" plane through (0, 0, 0) normal (0, 0, 1) x axis (1, 0, 0)
  line L1 (1.422, -1.5) -> (-1.422, -1.5)
  line L2 (1.422, 1.5) -> (1.422, -1.5)
  line L3 (-1.422, 1.5) -> (1.422, 1.5)
  line L4 (-1.422, -1.5) -> (-1.422, 1.5)
create_component "CreateComponent5" sketch "Sketch1"
sketch "Sketch1" plane through (0, 0, 0) normal (0, 0, 1) x axis (1, 0, 0)
  line L1 (1.9, -1.9) -> (-1.905, -1.9)
  line L2 (1.9, 1.905) -> (1.9, -1.9)
  line L3 (-1.905, 1.905) -> (1.9, 1.905)
  line L4 (-1.905, -1.9) -> (-1.905, 1.905)
create_component "CreateComponent6" sketch "Sketch1"
sketch "Sketch1" plane through (0, 0, 0) normal (0, 0, 1) x axis (1, 0, 0)
  line L1 (0.83, -0.47) -> (-0.838, -0.47)
  line L2 (0.83, 0.48) -> (0.83, -0.47)
  line L3 (-0.838, 0.48) -> (0.83, 0.48)
  line L4 (-0.838, -0.47) -> (-0.838, 0.48)
create_component "CreateComponent7" sketch "Sketch1"
sketch "Sketch1" plane through (0, 0, 0) normal (0, 0, 1) x axis (1, 0, 0)
  line L1 (1.9, -1.4) -> (-1.9, -1.4)
  line L2 (1.9, 1.4) -> (1.9, -1.4)
  line L3 (-1.9, 1.4) -> (1.9, 1.4)
  line L4 (-1.9, -1.4) -> (-1.9, 1.4)
create_component "CreateComponent8" sketch "Sketch1"
sketch "Sketch1" plane through (0, 0, 0) normal (0, 0, 1) x axis (1, 0, 0)
  line L1 (4.62, -5.08) -> (-4.62, -5.08)
  line L2 (4.62, 2.55) -> (4.62, -5.08)
  line L3 (-4.62, 2.55) -> (4.62, 2.55)
  line L4 (-4.62, -5.08) -> (-4.62, 2.55)
create_component "CreateComponent9" sketch "Sketch1"
sketch "Sketch1" plane through (0, 0, 0) normal (0, 0, 1) x axis (1, 0, 0)
  line L1 (3.5, -1) -> (-3.5, -1)
  line L2 (3.5, 2.4) -> (3.5, -1)
  line L3 (-3.5, 2.4) -> (3.5, 2.4)
  line L4 (-3.5, -1) -> (-3.5, 2.4)
create_component "CreateComponent10" sketch "Sketch1"
sketch "Sketch1" plane through (0, 0, 0) normal (0, 0, 1) x axis (1, 0, 0)
  line L1 (3.65, -3.25) -> (-3.65, -3.25)
  line L2 (3.65, 3.25) -> (3.65, -3.25)
  line L3 (-3.65, 3.25) -> (3.65, 3.25)
  line L4 (-3.65, -3.25) -> (-3.65, 3.25)
create_component "CreateComponent11" sketch "Sketch1"
sketch "Sketch1" plane through (0, 0, 0) normal (0, 0, 1) x axis (1, 0, 0)
  line L1 (3.465, -3.121) -> (-3.165, -3.121)
  line L2 (3.465, 3.121) -> (3.465, -3.121)
  line L3 (-3.165, 3.121) -> (3.465, 3.121)
  line L4 (-3.165, -3.121) -> (-3.165, 3.121)
create_component "CreateComponent12" sketch "Sketch1"
sketch "Sketch1" plane through (0, 0, 0) normal (0, 0, 1) x axis (1, 0, 0)
  line L1 (2.286, -1.016) -> (-2.286, -1.016)
  line L2 (2.286, 1.016) -> (2.286, -1.016)
  line L3 (-2.286, 1.016) -> (2.286, 1.016)
  line L4 (-2.286, -1.016) -> (-2.286, 1.016)
create_component "CreateComponent13" sketch "Sketch1"
sketch "Sketch1" plane through (0, 0, 0) normal (0, 0, 1) x axis (1, 0, 0)
  line L1 (2.616, -2.616) -> (-2.616, -2.616)
  line L2 (2.616, 2.616) -> (2.616, -2.616)
  line L3 (-2.616, 2.616) -> (2.616, 2.616)
  line L4 (-2.616, -2.616) -> (-2.616, 2.616)
create_component "CreateComponent14" sketch "Sketch1"
sketch "Sketch1" plane through (0, 0, 0) normal (0, 0, 1) x axis (1, 0, 0)
  line L1 (3.1, -2.594) -> (-3, -2.594)
  line L2 (3.1, 1.706) -> (3.1, -2.594)
  line L3 (-3, 1.706) -> (3.1, 1.706)
  line L4 (-3, -2.594) -> (-3, 1.706)
create_component "CreateComponent15" sketch "Sketch1"
sketch "Sketch1" plane through (0, 0, 0) normal (0, 0, 1) x axis (1, 0, 0)
  line L1 (5, -3.5) -> (-5, -3.5)
  line L2 (5, 4) -> (5, -3.5)
  line L3 (-5, 4) -> (5, 4)
  line L4 (-5, -3.5) -> (-5, 4)
create_component "CreateComponent16" sketch "Sketch1"
sketch "Sketch1" plane through (0, 0, 0) normal (0, 0, 1) x axis (1, 0, 0)
  line L1 (1, -0.7) -> (-1, -0.7)
  line L2 (1, 0.7) -> (1, -0.7)
  line L3 (-1, 0.7) -> (1, 0.7)
  line L4 (-1, -0.7) -> (-1, 0.7)
create_component "CreateComponent17" sketch "Sketch1"
sketch "Sketch1" plane through (0, 0, 0) normal (0, 0, 1) x axis (1, 0, 0)
  line L1 (13.2, -0.635) -> (-13.97, -0.635)
  line L2 (13.2, 0.635) -> (13.2, -0.635)
  line L3 (-13.97, 0.635) -> (13.2, 0.635)
  line L4 (-13.97, -0.635) -> (-13.97, 0.635)
create_component "CreateComponent18" sketch "Sketch1"
sketch "Sketch1" plane through (0, 0, 0) normal (0, 0, 1) x axis (1, 0, 0)
  line L1 (1.7, -1.7) -> (-2.35, -1.7)
  line L2 (1.7, 1.7) -> (1.7, -1.7)
  line L3 (-2.35, 1.7) -> (1.7, 1.7)
  line L4 (-2.35, -1.7) -> (-2.35, 1.7)
create_component "CreateComponent19" sketch "Sketch1"
sketch "Sketch1" plane through (0, 0, 0) normal (0, 0, 1) x axis (1, 0, 0)
  line L1 (0.75, -0.75) -> (-0.75, -0.75)
  line L2 (0.75, 0.75) -> (0.75, -0.75)
  line L3 (-0.75, 0.75) -> (0.75, 0.75)
  line L4 (-0.75, -0.75) -> (-0.75, 0.75)
create_component "CreateComponent20" sketch "Sketch1"
sketch "Sketch1" plane through (0, 0, 0) normal (0, 0, 1) x axis (1, 0, 0)
  line L1 (0.898, -0.898) -> (-0.898, -0.898)
  line L2 (0.898, 0.898) -> (0.898, -0.898)
  line L3 (-0.898, 0.898) -> (0.898, 0.898)
  line L4 (-0.898, -0.898) -> (-0.898, 0.898)
create_component "CreateComponent21" sketch "Sketch1"
sketch "Sketch1" plane through (0, 0, 0) normal (0, 0, 1) x axis (1, 0, 0)
  line L1 (2.1, -1.525) -> (-2.1, -1.525)
  line L2 (2.1, 1.525) -> (2.1, -1.525)
  line L3 (-2.1, 1.525) -> (2.1, 1.525)
  line L4 (-2.1, -1.525) -> (-2.1, 1.525)
create_component "CreateComponent22" sketch "Sketch1"
sketch "Sketch1" plane through (0, 0, 0) normal (0, 0, 1) x axis (1, 0, 0)
  line L1 (9, -8.936) -> (-9, -8.936)
  line L2 (9, 16.564) -> (9, -8.936)
  line L3 (-9, 16.564) -> (9, 16.564)
  line L4 (-9, -8.936) -> (-9, 16.564)
create_component "CreateComponent23" sketch "Sketch1"
sketch "Sketch1" plane through (0, 0, 0) normal (0, 0, 1) x axis (1, 0, 0)
  line L1 (0.95, -0.602) -> (-0.95, -0.602)
  line L2 (0.95, 0.602) -> (0.95, -0.602)
  line L3 (-0.95, 0.602) -> (0.95, 0.602)
  line L4 (-0.95, -0.602) -> (-0.95, 0.602)
create_component "CreateComponent24" sketch "Sketch1"
sketch "Sketch1" plane through (0, 0, 0) normal (0, 0, 1) x axis (1, 0, 0)
  line L1 (2, -2) -> (-2, -2)
  line L2 (2, 2) -> (2, -2)
  line L3 (-2, 2) -> (2, 2)
  line L4 (-2, -2) -> (-2, 2)
create_component "CreateComponent25" sketch "Sketch1"
sketch "Sketch1" plane through (0, 0, 0) normal (0, 0, 1) x axis (1, 0, 0)
  line L1 (14.16, -6.6) -> (-14.16, -6.6)
  line L2 (14.16, 4.6) -> (14.16, -6.6)
  line L3 (-14.16, 4.6) -> (14.16, 4.6)
  line L4 (-14.16, -6.6) -> (-14.16, 4.6)
create_component "CreateComponent26" sketch "Sketch1"
sketch "Sketch1" plane through (0, 0, 0) normal (0, 0, 1) x axis (1, 0, 0)
  line L1 (16.7, -6.6) -> (-16.7, -6.6)
  line L2 (16.7, 4.6) -> (16.7, -6.6)
  line L3 (-16.7, 4.6) -> (16.7, 4.6)
  line L4 (-16.7, -6.6) -> (-16.7, 4.6)
create_component "CreateComponent27" sketch "Sketch1"
sketch "Sketch1" plane through (0, 0, 0) normal (0, 0, 1) x axis (1, 0, 0)
  line L1 (62.113, 5.133) -> (48.313, 5.133)
  line L2 (62.113, 43.042) -> (62.113, 5.133)
  line L3 (48.313, 43.042) -> (62.113, 43.042)
  line L4 (48.313, 5.133) -> (48.313, 43.042)
create_component "CreateComponent28" sketch "Sketch1"
sketch "Sketch1" plane through (0, 0, 0) normal (0, 0, 1) x axis (1, 0, 0)
  line L1 (63.276, 0.349) -> (3.482, 0.349)
  line L2 (63.276, 44.164) -> (63.276, 0.349)
  line L3 (3.482, 44.164) -> (63.276, 44.164)
  line L4 (3.482, 0.349) -> (3.482, 44.164)
as_built_joint "As-built1"
named bodies: "Board", "CHIPLED_0603_NOOUTLINE", "0805-NO", "SOT23-DBV", "LED3535_FULLPADS", "0603-NO", "RESPACK_4X0603", "USB_C_CUSB31-CFM2AX-01-X", "SPST_TACTILE_RA", "PANASONIC_D", "TSSOP20", "SOLDERJUMPER_2WAY_OPEN_NOPASTE", "SMT_NUT_3MM", "JST_SH4", "JSTPH3", "SOD-323", "1X11_ROUND", "LGA16_3X3MM", "FIDUCIAL_1MM", "PCBFEAT-REV-040", "BTN_RKB2_4.6X2.8", "S3-WROOM32", "ALS-PT19-315C", "MOUNTINGHOLE_2.5_PLATED", "2X08_SHROUDEDSMT", "2X10_SMT_FEMALE", "S3_MATRIXPORTAL_BOT", "S3_MATRIXPORTAL_TOP"

design "Connector Bracket"
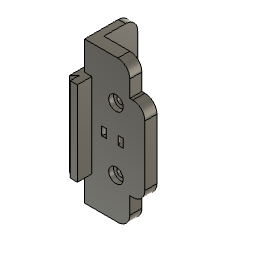
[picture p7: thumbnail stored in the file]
sketch "Sketch1" plane through (0, 0, 0) normal (0, 0, 1) x axis (1, 0, 0)
  line L1 (25, 5) -> (25, 0)
  line L2 (3, 5) -> (25, 5)
  line L3 (0, 19) -> (3, 19)
  line L4 (0, 11.75) -> (0, 19)
  line L5 (-2, 13.75) -> (0, 11.75)
  line L6 (-2, -4.25) -> (-2, 13.75)
  line L7 (0, -2.25) -> (-2, -4.25)
  line L8 (3, 5) -> (3, 19)
  line L9 (0, 0) -> (25, 0)
  line L10 (0, -2.25) -> (0, 0)
  line L11 (0, 13) -> (3, 13)
  line L12 (0, 0) -> (0, 13)
  line L13 (18.75, 0) -> (18.75, 5)
  line L14 (0, -6) -> (0, -2.25)
  line L15 (3, -6) -> (0, -6)
  line L16 (3, 0) -> (3, -6)
  point P1 (0, 0)
  point P12 (0, 0)
  point P13 (3, 13)
  point P15 (0, 0)
  point P16 (18.75, 5)
  point P17 (18.75, 0)
  point P20 (3, 0)
  point P5 (3, 19)
  point P11 (3, 19)
  point P8 (-2, 13.75)
  point P9 (-2, -4.25)
  point P2 (25, 0)
  point P3 (25, 5)
  point P4 (3, 5)
  point P14 (0, 13)
  point P6 (0, 19)
  perpendicular L1 L2
  perpendicular L3 L4
  perpendicular L3 L6
  vertical L8
  horizontal L2
  perpendicular L1 L9
  vertical L10
  vertical L6
  coincident P1 P12
  coincident L8 P13
  perpendicular L8 L11
  coincident L9 P15
  perpendicular L9 L12
  coincident L2 P16
  coincident L9 P17
  perpendicular L9 L13
  parallel L10 L14
  perpendicular L14 L15
  coincident L9 P20
  perpendicular L9 L16
  coincident P5 P11
  dimension "d1" angle L4 L5 = 45
  dimension "d2" distance P8 P9 = 18
  dimension "d53" distance L4 L6 = 2 (= "d65")
  dimension "d61" angle L7 L10 = 45
  dimension "d65" distance P9 L10 = 2
  dimension "d66" distance P2 P3 = 5
  dimension "d71" distance P3 P4 = 22
  dimension "d95" distance L12 L13 = 18.75
  dimension "d96" distance P13 P14 = 3
  dimension "d97" distance L14 L16 = 3
  dimension "d98" distance L9 L15 = 6
  dimension "d102" distance P5 P6 = 3
  dimension "d103" distance P4 P11 = 14
  dimension "d104" distance L9 L11 = 13
  dimension "d107" distance P6 P8 = 5.25
extrude "Extrude1" new body sketch "Sketch1" along normal blind 35 bodies "Connector Bracket"
sketch "Sketch2" plane through (0, 5, 0) normal (0, 1, 0) x axis (-1, 0, 0)
  line L1 (-3, 0) -> (-25, 0)
  line L2 (-25, 35) -> (-3, 35)
  line L3 (-25, 0) -> (-25, 35)
  line L4 (-13, 35) -> (-13, 0)
  line L5 (-3, 35) -> (-3, 0)
  line L6 (-3, 17.5) -> (-25, 17.5)
  line L7 (-19, 35) -> (-7, 35)
  line L8 (-19, 45) -> (-19, 35)
  line L9 (-7, 45) -> (-19, 45)
  line L10 (-7, 35) -> (-7, 45)
  line L11 (-7, 0) -> (-7, -10)
  line L12 (-19, -10) -> (-19, 0)
  circle C1 centre (-13, 30.5) radius 1.6
  circle C2 centre (-13, 4.5) radius 1.6
  circle C3 centre (-21, 25.5) radius 1.4
  circle C4 centre (-13, 30.5) radius 3
  circle C5 centre (-13, 4.5) radius 3
  point P7 (-13, 0)
  point P8 (-13, 35)
  point P6 (-13, 30.5)
  point P9 (-13, 4.5)
  point P13 (-25, 17.5)
  point P14 (-3, 17.5)
  point P15 (-7, 35)
  point P20 (-7, 0)
  point P16 (-19, 35)
  point P21 (-19, 0)
  point P17 (-19, 45)
  point P22 (-19, -10)
  point P18 (-7, 45)
  point P19 (-7, -10)
  point P10 (-21, 25.5)
  point P11 (-13, 30.5)
  vertical L4
  coincident L1 P7
  coincident L2 P8
  coincident P6 L4
  coincident L4 P9
  concentric C1 C4
  concentric C2 C5
  midpoint L3 P13
  midpoint L5 P14
  horizontal L7
  vertical L8
  horizontal L9
  vertical L10
  coincident L2 P15
  symmetric L6 P15 P20
  symmetric L6 P16 P21
  symmetric L6 P17 P22
  symmetric L6 P18 P19
  dimension "d12" diameter C1 = 3.2
  dimension "d14" diameter C2 = 3.2
  dimension "d19" diameter C3 = 2.8
  dimension "d24" distance P6 P10 = 5
  dimension "d27" diameter C4 = 6
  dimension "d28" diameter C5 = 6
  dimension "d67" distance P11 L5 = 10
  dimension "d68" distance P10 L5 = 18
  dimension "d69" distance P11 L6 = 13
  dimension "d70" distance P9 L6 = 13
  dimension "d78" distance P8 L9 = 10
  dimension "d79" distance P17 P18 = 12
  dimension "d80" distance P8 L8 = 6
extrude "Extrude2" cut sketch "Sketch2" profile of C1 C2 against normal blind 5
fillet "Fillet1" radius 5
extrude "Extrude3" cut sketch "Sketch2" profile of C1 C2 C4 C5 blind -2 from offset -3
extrude "Extrude4" cut sketch "Sketch2" profile of C3 against normal blind 3
work_plane "WorkPlane2" AlongDistance -17.5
